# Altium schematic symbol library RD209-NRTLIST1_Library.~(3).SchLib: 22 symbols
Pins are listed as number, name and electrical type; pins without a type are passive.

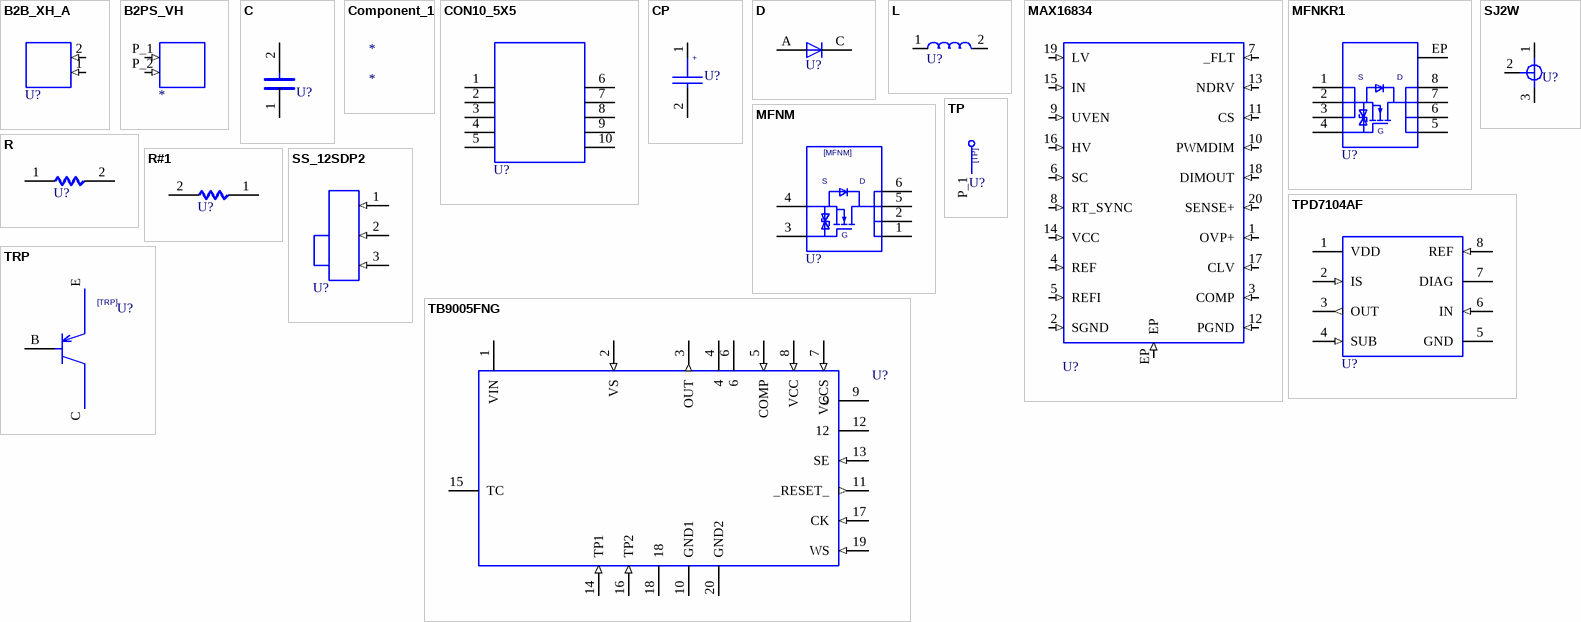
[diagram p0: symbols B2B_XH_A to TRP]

## B2B_XH_A
designator U?  (value not drawn)
SAVECOUNT: 1; COMP: B2B-XH-A; UPDATEUSER: t5459927; UPDATETIME: 17:22:42; OriginalSymbolOrigin: (0,0); Altium-Right: 30
pins: 1 (in), 2 (in)

## B2PS_VH
designator *  (value not drawn)
SAVECOUNT: 1; COMP: B2PS-VH; UPDATEUSER: t5459927; UPDATETIME: 17:22:42; OriginalSymbolOrigin: (0,0); Altium-Right: 30
pins: P_1 1 (in), P_2 2 (in)

## C
designator U?  (value not drawn)
TIME: 17:22:43; UPDATEUSER: t5459927; SAVECOUNT: 1; OriginalSymbolOrigin: (2540,7620); Altium-Right: 20; Altium-Bottom: 10
pins: 1, 2

## Component_1
designator *

## CON10_5X5
designator U?  (value not drawn)
TIME: 17:22:42; SAVECOUNT: 1; SAVEAREA0: -6378,-413,31795,20718; UPDATEUSER: t5459927; OriginalSymbolOrigin: (5080,22860); Altium-Right: 60; Altium-Bottom: 80
pins: 1, 2, 3, 4, 5, 6, 7, 8, 9, 10

## CP
designator U?  (value not drawn)
TIME: 17:22:43; SAVECOUNT: 1; SAVEAREA0: -1450,-153,20294,13055; UPDATEUSER: t5459927; OriginalSymbolOrigin: (2540,10160); Altium-Right: 20
pins: 1 2, 2 1

## D
designator U?  (value not drawn)
SAVEAREA0: -225,-91,12804,7836; SAVECOUNT: 3; TIME: 14:49:55; UPDATEUSER: 19870035; UPDATETIME: 14:20:16; OriginalSymbolOrigin: (5080,5080); Altium-Right: 10; Altium-Bottom: 20
pins: A, C

## L
designator U?  (value not drawn)
TIME: 17:22:43; UPDATEUSER: t5459927; SAVECOUNT: 1; OriginalSymbolOrigin: (2540,5080); Altium-Right: 30; Altium-Bottom: 20
pins: 1, 2

## MAX16834
designator U?  (value not drawn)
SAVECOUNT: 1; SAVEAREA0: -47937,-54417,76568,2975; UPDATEUSER: t5459927; UPDATETIME: 17:22:42; OriginalSymbolOrigin: (0,0); Altium-Right: 120; Altium-Bottom: 200
pins: 1 OVP+ (in), 2 SGND (in), 3 COMP (in), 4 REF (in), 5 REFI (in), 6 SC (in), 7 _FLT (in), 8 RT_SYNC (in), 9 UVEN (in), 10 PWMDIM (in), 11 CS (in), 12 PGND (in), 13 NDRV (in), 14 VCC (in), 15 IN (in), 16 HV (in), 17 CLV (in), 18 DIMOUT (in), 19 LV (in), 20 SENSE+ (in), EP (in)

## MFNKR1
designator U?  (value not drawn)
TIME: 17:22:43; SAVECOUNT: 2; SAVEAREA0: -5755,-491,27794,24105; UPDATETIME: 09:26:31; UPDATEUSER: t5459927; OriginalSymbolOrigin: (5080,20320); Altium-Right: 50; Altium-Bottom: 70
pins: 1, 2, 3, 4, 5, 6, 7, 8, EP

## MFNM
designator U?  (value not drawn)
TIME: 17:22:43; SAVECOUNT: 1; SAVEAREA0: -6986,-322,29385,23602; UPDATEUSER: t5459927; OriginalSymbolOrigin: (5080,20320); Altium-Right: 50; Altium-Bottom: 70
pins: 1, 2, 3, 4, 5, 6

## R
designator U?  (value not drawn)
TIME: 17:22:43; UPDATEUSER: t5459927; SAVECOUNT: 1; OriginalSymbolOrigin: (5080,5080); Altium-Right: 20
pins: 1, 2

## R#1
designator U?, comment R  (value not drawn)
TIME: 17:22:43; UPDATEUSER: t5459927; SAVECOUNT: 1; OriginalSymbolOrigin: (5080,5080); Altium-Right: 20
pins: 1 2, 2 1

## SJ2W
designator U?  (value not drawn)
SAVECOUNT: 1; SAVEAREA0: -15743,-4510,23437,11881; UPDATEUSER: t5459927; UPDATETIME: 17:22:42; OriginalSymbolOrigin: (2540,7620); Altium-Right: 20
pins: 1, 2, 3

## SS_12SDP2
designator U?  (value not drawn)
SAVECOUNT: 1; COMP: SS-12SDP2; UPDATEUSER: t5459927; UPDATETIME: 17:22:42; OriginalSymbolOrigin: (0,0); Altium-Right: 30; Altium-Bottom: 60
pins: 1 (in), 2 (in), 3 (in)

## TB9005FNG
designator U?  (value not drawn)
SAVECOUNT: 3; SAVEAREA0: -26622,-27385,86055,19754; UPDATEUSER: t5459927; UPDATETIME: 09:48:39; TIME: 17:22:42; OriginalSymbolOrigin: (0,0); Altium-Right: 240; Altium-Bottom: 130
pins: 1 VIN, 2 VS (in), 3 OUT (out), 4, 5 COMP (in), 6, 7 VCCS (in), 8 VCC (in), 9, 10 GND1, 11 _RESET_ (out), 12, 13 SE (in), 14 TP1 (in), 15 TC, 16 TP2 (in), 17 CK (in), 18, 19 WS (in), 20 GND2

## TP
designator U?  (value not drawn)
TIME: 17:22:42; SAVECOUNT: 1; SAVEAREA0: -242,-92,12810,7836; UPDATEUSER: t5459927; OriginalSymbolOrigin: (0,7620); Altium-Right: 20; Altium-Bottom: 30
pins: P_1 1

## TPD7104AF
designator U?  (value not drawn)
SAVECOUNT: 1; UPDATEUSER: t5459927; UPDATETIME: 17:22:42; OriginalSymbolOrigin: (0,0); Altium-Right: 80
pins: 1 VDD, 2 IS (in), 3 OUT (out), 4 SUB (in), 5 GND, 6 IN (in), 7 DIAG, 8 REF (in)

## TRP
designator U?  (value not drawn)
TIME: 17:22:43; SAVECOUNT: 1; SAVEAREA0: -5466,-244,29263,20886; UPDATEUSER: t5459927; OriginalSymbolOrigin: (5080,22860); Altium-Right: 20; Altium-Bottom: 100
pins: B, C, E

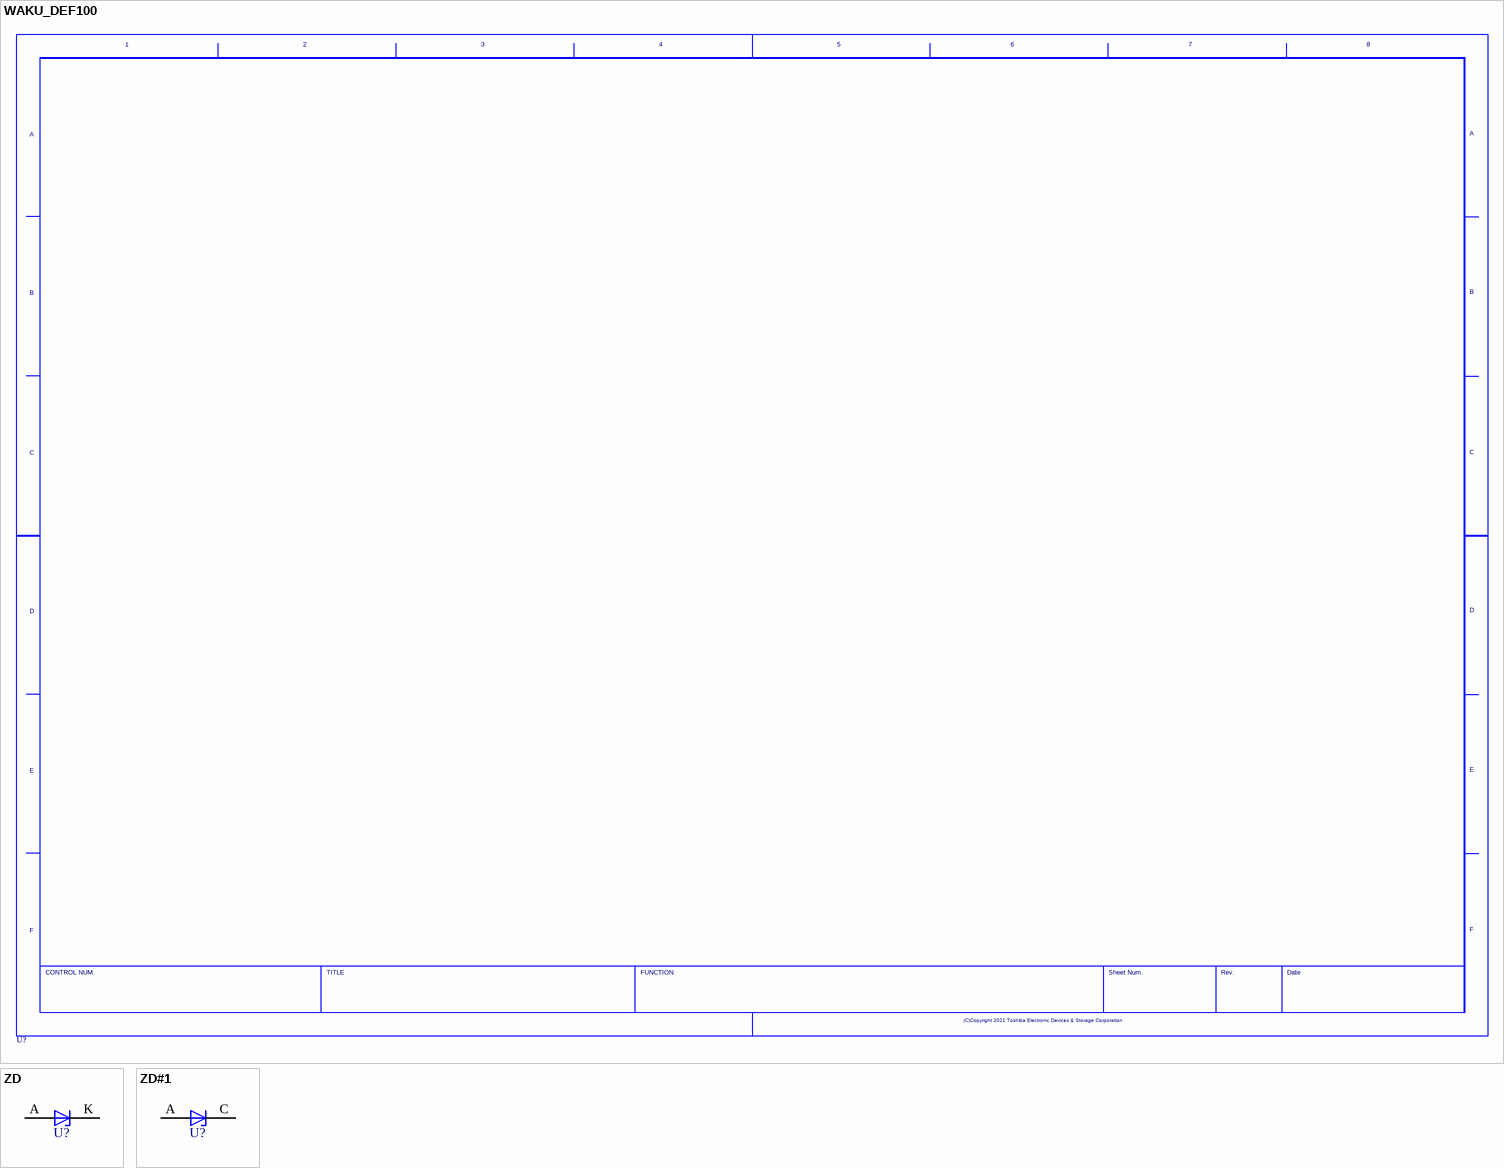
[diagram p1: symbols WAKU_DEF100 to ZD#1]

## WAKU_DEF100
designator U?  (value not drawn)
PLOTTIME: HH:MM; SAVEAREA0: 147884,-66467,487065,89883; TIME: 14:30:25; UPDATEUSER: t5459927; UPDATETIME: 10:21:24; SAVECOUNT: 7; OriginalSymbolOrigin: (10160,284480); Altium-Right: 1570; Altium-Bottom: 1070

## ZD
designator U?  (value not drawn)
TIME: 17:22:43; SAVECOUNT: 1; SAVEAREA0: -4630,-153,17114,13055; UPDATEUSER: t5459927; OriginalSymbolOrigin: (5080,5080); Altium-Right: 10; Altium-Bottom: 20
pins: A, K C

## ZD#1
designator U?, comment ZD  (value not drawn)
TIME: 17:22:43; SAVECOUNT: 1; SAVEAREA0: -4630,-153,17114,13055; UPDATEUSER: t5459927; OriginalSymbolOrigin: (5080,5080); Altium-Right: 10; Altium-Bottom: 20
pins: A, C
